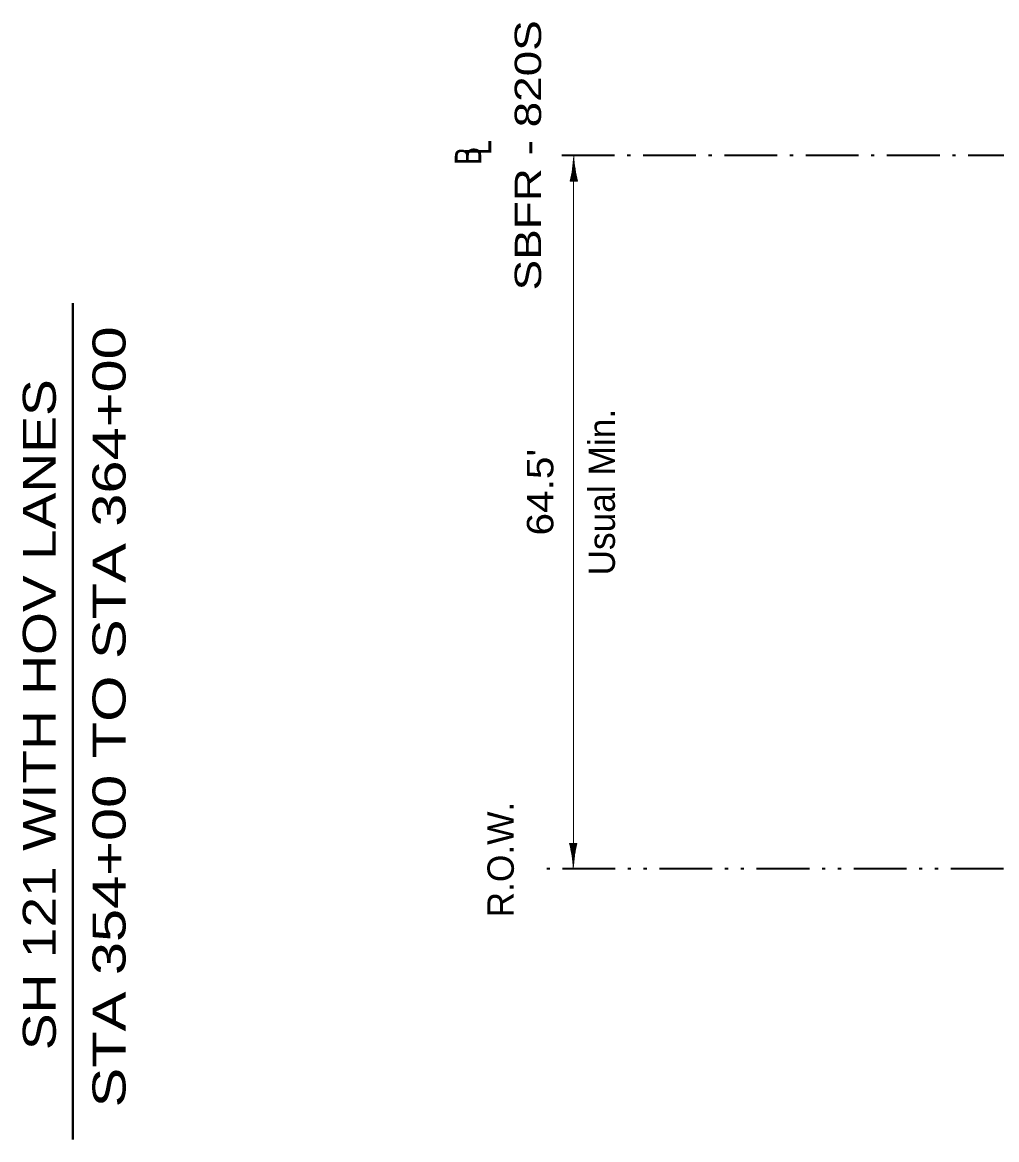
# Model space of a CAD drawing. Extents: x 2363427 to 2368559, y 6957299 to 6980140.
# Drawn here: x 2365654 to 2366171, y 6965032 to 6965625 of the extents above; entities that cross this region are included whole.
import ezdxf
from ezdxf.enums import TextEntityAlignment as Align

# ---------------------------------------------------------------- set-up
doc = ezdxf.new("R2010")
doc.units = 0
doc.header["$LTSCALE"] = 5.6
doc.linetypes.add('DASH_DOUBLE_DOT', pattern=[9.2, 5, -1.2, 0.3, -1.2, 0.3, -1.2])
doc.linetypes.add('DOT_DASHED', pattern=[7.7, 5, -1.2, 0.3, -1.2])
doc.layers.add('3', color=7, linetype='Continuous', lineweight=35)
doc.layers.add('4', color=7, linetype='Continuous', lineweight=13)

msp = doc.modelspace()

# ---------------------------------------------------------------- linework, layer by layer
at = {"layer": '3', "linetype": 'DOT_DASHED'}
msp.add_line((2366529.101, 6965553.981), (2365939.21, 6965553.981), dxfattribs=at)
at = {"layer": '3', "linetype": 'DASH_DOUBLE_DOT'}
msp.add_line((2366432.49, 6965175.413), (2365932.627, 6965175.413), dxfattribs=at)
at = {"layer": '4'}
for p, q in [((2365946.426, 6965540.253), (2365946.426, 6965548.863)), ((2365946.688, 6965186.439), (2365946.688, 6965551.075)), ((2365946.926, 6965540.253), (2365946.926, 6965552.817)), ((2365947.426, 6965540.253), (2365947.426, 6965547.603)), ((2365945.426, 6965540.253), (2365945.426, 6965542.635)), ((2365945.926, 6965540.253), (2365945.926, 6965545.115)), ((2365947.926, 6965540.253), (2365947.926, 6965544.529)), ((2365948.426, 6965540.253), (2365948.426, 6965541.837)), ((2365948.776, 6965540.253), (2365944.946, 6965540.253)), ((2365944.662, 6965188.991), (2365948.492, 6965188.991)), ((2365945.012, 6965188.991), (2365945.012, 6965187.407)), ((2365945.512, 6965188.991), (2365945.512, 6965184.715)), ((2365946.012, 6965188.991), (2365946.012, 6965181.641)), ((2365946.512, 6965188.991), (2365946.512, 6965176.427)), ((2365947.012, 6965188.991), (2365947.012, 6965180.381)), ((2365947.512, 6965188.991), (2365947.512, 6965184.129)), ((2365948.012, 6965188.991), (2365948.012, 6965186.609))]:
    msp.add_line(p, q, dxfattribs=at)
at = {"layer": '4', "lineweight": 40}
msp.add_line((2365681.161, 6965031.766), (2365681.161, 6965475.544), dxfattribs=at)
at = {"layer": '4'}
for centre, start, end in [((2365874.737, 6965557.147), 346.47039, 357.15644), ((2366018.984, 6965557.147), 182.84356, 193.52961), ((2365874.454, 6965172.098), 2.84356, 13.52961), ((2366018.701, 6965172.098), 166.47039, 177.15644)]:
    msp.add_arc(centre, 72.212, start, end, dxfattribs=at)

# ---------------------------------------------------------------- texts
for s, height, width, p in [('SBFR - 820S', 14, 1.3, (2365929.519, 6965554.037)), ('L', 14, 0.75, (2365903.135, 6965558.247)), ('B', 14, 0.75, (2365897.745, 6965553.758)), ('STA 354+00 TO STA 364+00', 17.5, 1.35, (2365709.035, 6965256.093)), ('SH 121 WITH HOV LANES', 17.5, 1.25, (2365672.055, 6965257.259)), ("64.5'", 14, 1.15, (2365936.006, 6965375.32))]:
    msp.add_text(s, height=height, rotation=90, dxfattribs=dict(at, width=width)).set_placement(p, align=Align.CENTER)
for s, p in [('Usual Min.', (2365968.678, 6965375.321)), ('R.O.W.', (2365915.038, 6965180.38))]:
    msp.add_text(s, height=14, rotation=90, dxfattribs=at).set_placement(p, align=Align.CENTER)

doc.saveas('drawing.dxf')
